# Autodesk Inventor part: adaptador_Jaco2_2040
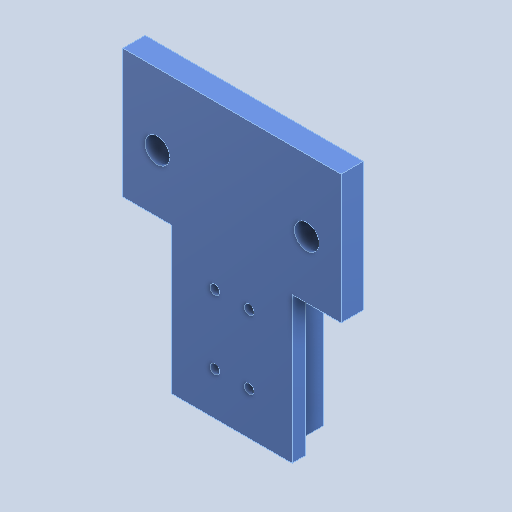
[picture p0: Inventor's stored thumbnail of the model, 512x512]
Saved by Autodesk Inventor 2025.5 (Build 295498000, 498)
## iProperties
Created: 2026-10
Part Number: adaptador_Jaco2_2040
Material: Genérico
Document SubType Name: Modeling
Designer: Luis M
Density: 1 g/cm^3
Appearance: Valor por defecto
Author: Luis M
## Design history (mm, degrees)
feature "Base1"
node "Sólido1"
